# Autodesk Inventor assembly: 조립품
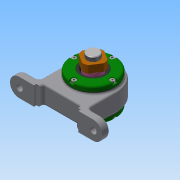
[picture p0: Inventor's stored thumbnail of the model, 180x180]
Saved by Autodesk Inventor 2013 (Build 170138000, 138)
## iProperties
Created: 2019-05
Part Number: 조립품
Document SubType Name: Assembly
Designer: Gpr
Author: Gpr
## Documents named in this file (13)
- C:\Users\Administrator\Desktop\490504V1001\조립품.iam
- C:\Users\Administrator\Desktop\490504V1001\본체.ipt
- C:\Users\Administrator\Desktop\490504V1001\개스킷.ipt
- C:\Users\Administrator\Desktop\490504V1001\그리스니플 M6.ipt
- 그리스니플  M6.ipt
- C:\Users\Administrator\Desktop\490504V1001\그리스니플개스킷.ipt
- C:\Users\Administrator\Desktop\490504V1001\베어링너트.ipt
- C:\Users\Administrator\Desktop\490504V1001\볼트 M4.ipt
- C:\Users\Administrator\Desktop\490504V1001\앵귤러 볼 베어링 7205.ipt
- C:\Users\Administrator\Desktop\490504V1001\오일 실 28 40 5 B.ipt
- C:\Users\Administrator\Desktop\490504V1001\축.ipt
- C:\Users\Administrator\Desktop\490504V1001\칼라.ipt
- C:\Users\Administrator\Desktop\490504V1001\커버.ipt
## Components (4 placed, 3 different names)
1. 개스킷:1
2. 그리스니플  M6:1 — 각도:3
3. 그리스니플개스킷:1
4. 개스킷:2
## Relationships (1: Angle 1)
- 각도:3 [Angle]: 그리스니플  M6:1
